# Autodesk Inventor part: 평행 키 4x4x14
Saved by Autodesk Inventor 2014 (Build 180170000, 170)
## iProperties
Created: 2026-04
Part Number: 평행 키 4x4x14
Material: 일반
Document SubType Name: Modeling
Designer: dg
Density: 1 g/cm^3
Appearance: 기본값
Author: dg
Author: jhkim
Description: 키 및 해당 키홈
Creation Date: 2026-03-26
Sending System: Autodesk Inventor 2026
Preprocessor: ST-DEVELOPER v20.1
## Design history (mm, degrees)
node "평행 키 4x4x141"
body "Solid1"
node "기준1"
